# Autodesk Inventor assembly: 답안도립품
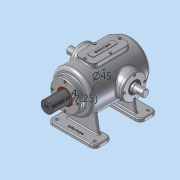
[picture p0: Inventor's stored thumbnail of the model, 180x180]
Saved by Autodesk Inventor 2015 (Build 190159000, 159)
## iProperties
Created: 2016-02
Part Number: 답안도립품
Document SubType Name: Assembly
Designer: Administrator
Mass: 8191.31 g
Surface Area: 4241.85 cm^2
Volume: 1855.5 cm^3
Density: 4.4146 g/cm^3
Author: Administrator
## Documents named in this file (15)
- C:\Users\Administrator\Desktop\360220V1017\답안도립품.iam
- C:\Users\Administrator\Desktop\360220V1017\본체.ipt
- C:\Users\Administrator\Desktop\360220V1017\슬라이드 커버.ipt
- C:\Users\Administrator\Desktop\360220V1017\볼트 M4x0.7.ipt
- C:\Users\Administrator\Desktop\360220V1017\축 커버.ipt
- C:\Users\Administrator\Desktop\360220V1017\오일실.ipt
- 오일실.ipt
- C:\Users\Administrator\Desktop\360220V1017\상부커버.ipt
- C:\Users\Administrator\Desktop\360220V1017\육각머리볼트 M4.ipt
- C:\Users\Administrator\Desktop\360220V1017\베어링 6205.ipt
- 베어링 6205.ipt
- C:\Users\Administrator\Desktop\360220V1017\편심축.ipt
- C:\Users\Administrator\Desktop\360220V1017\부시.ipt
- C:\Users\Administrator\Desktop\360220V1017\가변스프링.ipt
- C:\Users\Administrator\Desktop\360220V1017\슬라이드.ipt
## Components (13 placed, 2 different names)
1. 가변스프링:1
2. M4x0.7:1
3. M4x0.7:2
4. M4x0.7:3
5. M4x0.7:4
6. M4x0.7:5
7. M4x0.7:6
8. M4x0.7:7
9. M4x0.7:8
10. M4x0.7:9
11. M4x0.7:10
12. M4x0.7:11
13. M4x0.7:12
